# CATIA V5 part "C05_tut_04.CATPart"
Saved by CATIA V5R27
Part number: Part1
Bounding box of the stored display mesh (mm): x -150 to 0, y -16 to 54, z 0 to 75
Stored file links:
  E:\_Deepak\2017_Deepak\CATIA\Resources\Tutorial Files\Tutorials\c05_catia_v5_6r2016_tut\C05_tut_04.CATPart
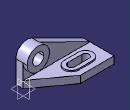
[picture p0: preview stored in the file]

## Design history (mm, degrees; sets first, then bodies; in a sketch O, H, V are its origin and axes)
Body1 (main body)
  Sketch1 on xy-plane, origin (0, 0, 0), H (1, 0, 0), V (0, 1, 0)
    line L1 (0, 0) -> (-150, 0)
    line L2 (-150, 0) -> (-150, 54)
    line L3 (-150, 54) -> (-75, 54)
    line L4 (-75, 54) -> (0, 0)
    length L2 = 54
    length L3 = 75
    length L1 = 150
    vertical: L2 V
    horizontal: L3 H, L1 H
  Pad1: profile Sketch1, direction (0, 0, 1), length 16
  Sketch2 on end face of Pad1, origin (0, 0, 16), H (1, 0, 0), V (0, 1, 0)
    construction line L1 (-114, 26) -> (-82, 26)
    point P1 (-114, 26)
    line L2 (-114, 42) -> (-82, 42)
    line L3 (-82, 10) -> (-114, 10)
    arc A1 centre (-82, 26) radius 16 from (-82, 42) to (-82, 10) cw
    arc A2 centre (-114, 26) radius 16 from (-114, 10) to (-114, 42) cw
    reference projected line E1 (-150, 0) -> (0, 0) from edge [face of Pad1 from Sketch1.L1 | end face of Pad1]
    reference projected line E2 (-150, 54) -> (-150, 0) from edge [face of Pad1 from Sketch1.L2 | end face of Pad1]
    distance L1 L2 = 16
    distance L3 E1 = 10
    length L2 = 32
    distance P1 E2 = 36
    horizontal: L1 H
    tangency: A1 L2, A2 L2, A1 L3, A2 L3
  Pad2: profile Sketch2, direction (0, 0, 1), length 3
  Sketch3 on face of Pad1 from Sketch1.L1, origin (0, 0, 0), H (1, 0, 0), V (0, 0, 1)
    line L1 (0, 0) -> (0, 50)
    arc A1 centre (-25, 50) radius 25 from (0, 50) to (-36.0939, 72.4037) ccw
    line L2 (-36.0939, 72.4037) -> (-150, 16)
    point P4 (-150, 16)
    line L3 (-150, 16) -> (-150, 0)
    point P5 (-150, 0)
    line L4 (-150, 0) -> (0, 0)
    reference projected line E1 (-150, 0) -> (-150, 16) from edge [face of Pad1 from Sketch1.L1 | face of Pad1 from Sketch1.L2]
    reference projected line E2 (-150, 16) -> (0, 16) from edge [face of Pad1 from Sketch1.L1 | end face of Pad1]
    radius A1 = 25
    length L1 = 50
    vertical: L1 V, L3 V
    tangency: A1 L1, L2 A1
    coincidence: P5 H, L3 E1, P4 E2
    horizontal: L4 H
  Pad3: profile Sketch3, direction (0, -1, 0), length 16
  Sketch4 on start face of Pad3, origin (0, 0, 0), H (-1, 0, 0), V (0, 0, 1)
    circle A1 centre (25, 50) radius 25
    reference projected arc E1 centre (25, 50) radius 25 from (37.6005, 71.5923) to (0, 50) ccw from edge [start face of Pad3 | face of Pad3 from Sketch3.A1]
    radius A1 = 25
    concentricity: A1 E1
  Pad4: profile Sketch4, direction (0, 1, 0), length 9
  Sketch5 on end face of Pad4, origin (0, 9, 0), H (-1, 0, 0), V (0, 0, 1)
    circle A1 centre (25, 50) radius 12.5
    reference projected circle E1 centre (25, 50) radius 25 from edge [face of Pad4 from Sketch4.A1 | end face of Pad4]
    radius A1 = 12.5
    concentricity: A1 E1
  Pocket1: profile Sketch5, direction (0, -1, 0), through (limit type 3)
  Sketch6 on end face of Pad2, origin (0, 0, 19), H (1, 0, 0), V (0, 1, 0)
    construction line L1 (-114, 26) -> (-82, 26)
    line L2 (-114, 34) -> (-82, 34)
    line L3 (-82, 18) -> (-114, 18)
    arc A1 centre (-82, 26) radius 8 from (-82, 34) to (-82, 18) cw
    arc A2 centre (-114, 26) radius 8 from (-114, 18) to (-114, 34) cw
    reference projected arc E1 centre (-114, 26) radius 16 from (-114, 42) to (-114, 10) ccw from edge [face of Pad2 from Sketch2.A2 | end face of Pad2]
    reference projected arc E2 centre (-82, 26) radius 16 from (-82, 10) to (-82, 42) ccw from edge [face of Pad2 from Sketch2.A1 | end face of Pad2]
    distance L2 L1 = 8
    horizontal: L1 H
    tangency: A1 L2, A2 L2, A1 L3, A2 L3
    concentricity: A2 E1, A1 E2
  Pocket2: profile Sketch6, direction (0, 0, -1), through (limit type 3)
